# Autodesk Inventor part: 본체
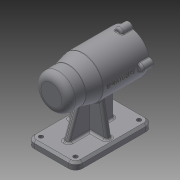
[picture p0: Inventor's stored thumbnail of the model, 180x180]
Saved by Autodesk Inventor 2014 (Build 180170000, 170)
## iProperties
Created: 2019-07
Part Number: 본체
Material: Generic
Document SubType Name: Modeling
Designer: kh
Density: 1 g/cm^3
Appearance: Default
Author: kh
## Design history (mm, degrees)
sketch "Sketch1"
  geometry: L1 (0, 0)-(112, 0); L2 (0, 0)-(0, 25); L3 (0, 25)-(25, 25); L4 (25, 25)-(45, 30); L5 (45, 30)-(112, 30); L6 (112, 30)-(112, 21); L7 (112, 21)-(97, 21); L8 (97, 21)-(97, 24); L9 (97, 24)-(43, 24); L10 (43, 24)-(43, 21); L11 (43, 21)-(31, 21); L12 (31, 21)-(31, 17.5); L13 (31, 17.5)-(13, 17.5); L14 (13, 17.5)-(13, 16); L15 (13, 16)-(9, 16); L16 (9, 16)-(9, 10.5); L17 (9, 10.5)-(6, 10.5); L18 (6, 10.5)-(6, 0)
  constraints: 36 end point, 8 parallel, 5 perpendicular, 2 horizontal, 1 collinear, 1 point on line, 1 vertical, 1 vertical alignment
  dimensions: "d0" = 112 distance of L1.start L1.end; "d1" = 50 diameter of L3 L1; "d2" = 21 diameter of L17 L1; "d3" = 32 diameter of L15 L1; "d4" = 35 diameter of L13 L1; "d5" = 42 diameter of L11 L1; "d6" = 48 diameter of L9 L1; "d7" = 42 diameter of L7 L1; "d8" = 25 distance of L2.end L3.end; "d9" = 45 distance from line of L4.end L2; "d10" = 60 diameter of L5 L1; "d11" = 3 distance of L16.end L17.end; "d12" = 4 distance of L14.end L15.end; "d13" = 18 distance of L12.end L13.end; "d14" = 12 distance of L10.end L11.end; "d15" = 54 distance of L8.end L9.end; "d16" = 15 distance of L6.end L7.end
revolve "Revolution1" sketch "Sketch1" stored, may be unused: angle "d17" = 90 deg
sketch "Sketch2"
  geometry: L1 (-35, -70)-(35, -70); L2 (35, -70)-(35, -80); L3 (35, -80)-(-35, -80); L4 (-35, -80)-(-35, -70); C1 r 25 at (0, 0) reference; 1 further point
  constraints: 8 end point, 2 parallel, 1 horizontal, 1 midpoint, 1 perpendicular, 1 vertical alignment
  dimensions: "d18" = 80 distance from line of L3 C1.centre; "d19" = 10 distance of L3.end L1.start; "d20" = 70 distance of L2.end L3.end
extrude "Extrusion1" join sketch "Sketch2" distance "d21" = 112; taper "d22" = 0 deg
fillet "Fillet1" dims "d23" = 10
workplane "Work Plane1"
sketch "Sketch3"
  geometry: L1 (26.67, 45.8)-(10, 0); L2 (77, 45.8)-(77, 0); L3 (26.67, 45.8)-(77, 45.8); L4 (10, 0)-(77, 0); L5 (-10, -10)-(-10, 0) reference; L6 (102, 0)-(102, -10) reference; L7 (0, 0)-(92, 0) reference; 1 further point
  constraints: 8 end point, 1 collinear, 1 horizontal, 1 perpendicular, 1 vertical
  dimensions: "d24" = 20 distance from line of L1.end L5; "d25" = 25 distance between parallel lines of L6 L2; "d26" = 110 deg angle of L7 L1; "d27" = 45.8 distance of L2.start L2.end
extrude "Extrusion2" join sketch "Sketch3" stored distance "d28" = 8; taper "d29" = 0 deg
workplane "Work Plane2"
sketch "Sketch4"
  geometry: L1 (-25, -70)-(25, -70) reference; L2 (-35, -80)-(-35, -70) reference; L3 (-19.654, -22.666)-(-28, -70); L4 (-35, -70)-(-25, -70) reference; L5 (0, -70)-(0, -53.293); L6 (19.654, -22.666)-(28, -70); 2 further points
  constraints: 6 end point, 2 symmetric about line, 1 midpoint, 1 perpendicular, 1 point on line, 2 other
  dimensions: "d31" = 7 distance of L3.end L2.end; "d32" = 100 deg angle of L4 L3
feature "Rib1" dims "d33" = 1, "d34" = 8, "d35" = 0, "d36" = 0, "d37" = 1, "d38" = 1
feature "Rib2" dims "d39" = 1, "d40" = 8, "d41" = 0, "d42" = 0, "d43" = 1, "d44" = 1
sketch "Sketch5"
  geometry: C1 r 6 at (0, 30); 1 further point
  constraints: 2 vertical alignment, 1 centre point, 1 other
  dimensions: "d46" = 6 radius of C1
extrude "Extrusion3" join sketch "Sketch5" distance "d47" = 16; taper "d48" = 0 deg
fillet "Fillet2" dims "d49" = 3
fillet "Fillet3" dims "d50" = 1
pattern_circular "Circular Pattern1" dims "d52" = 360 deg
fillet "Fillet4" dims "d56" = 3
fillet "Fillet5" dims "d57" = 0.3
fillet "Fillet6" dims "d58" = 3
chamfer "Chamfer1" distance "d59" = 1; stored, may be unused: second distance "d60" = 2, angle "d61" = 45 deg
fillet "Fillet7" dims "d62" = 3
chamfer "Chamfer2" distance "d63" = 3; stored, may be unused: second distance "d64" = 2, angle "d65" = 45 deg
fillet "Fillet8" dims "d66" = 3
fillet "Fillet9" dims "d67" = 3
sketch "Sketch7"
  geometry: C1 r 3 at (0, 57); C2 r 3 at (0, 7); C3 r 3 at (92, 57); C4 r 3 at (92, 7); A1 r 7 centre (0, 7) between (-7, 7) and (0, 0) reference; A2 r 7 centre (92, 7) between (92, 0) and (99, 7) reference; A3 r 7 centre (92, 57) between (99, 57) and (92, 64) reference; A4 r 7 centre (0, 57) between (0, 64) and (-7, 57) reference; 1 further point
  constraints: 4 centre point, 4 coincident, 3 equal radius
  dimensions: "d68" = 6 diameter of C1
extrude "Extrusion5" cut sketch "Sketch7" stored distance "d69" = 0; taper "d70" = 0 deg
fillet "Fillet10" dims "d71" = 10
fillet "Fillet11" dims "d72" = 3
workplane "Work Plane4"
sketch "Sketch8"
  geometry: L1 (102, 86.771)-(102, 109.226) reference; 2 further points
  constraints: 1 horizontal alignment, 1 other
  dimensions: "d74" = 42 distance from line of point (60, 80) L1
emboss "Emboss1" sketch "Sketch8" dims "d0" = 112, "d1" = 50, "d2" = 21, "d3" = 32, "d4" = 35, "d5" = 42, "d6" = 48, "d7" = 42, "d8" = 25, "d9" = 45, "d10" = 60, "d11" = 3, "d12" = 4, "d13" = 18, "d14" = 12, "d15" = 54, "d16" = 15, "d75" = 0.5, "d76" = 0
hole "Hole1" diameter "d79" = 3.459; stored, may be unused: countersink angle "d83" = 90 deg, drill point angle "d85" = 118 deg; dims "d77" = 10, "d78" = 10, "d80" = 8, "d81" = 4, "d82" = 2, "d84" = 11
pattern_circular "Circular Pattern2" dims angle "d87" = 360 deg
body "Solid1"
other parameters: "d73" = 16.25
